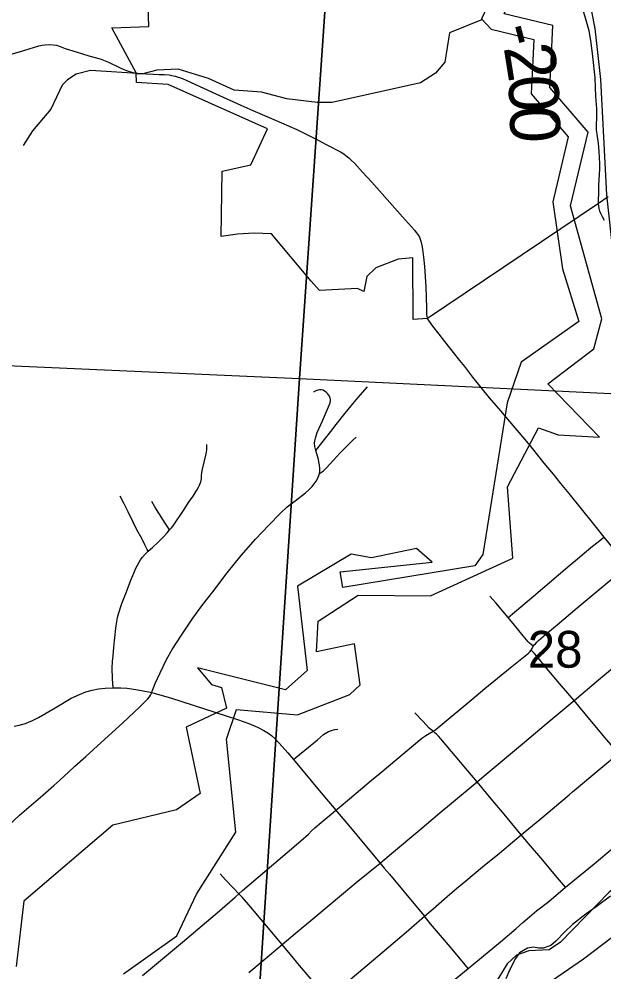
# Model space of a CAD drawing. Extents: x 0 to 34, y 0 to 22.
# Drawn here: x 6.959 to 7.626, y 19.29 to 20.375 of the extents above; entities that cross this region are included whole.
import ezdxf

# ---------------------------------------------------------------- set-up
doc = ezdxf.new("R2010")
doc.units = 0
for name, color, linetype in [('Default', 7, 'Continuous'), ('GM_X_City_Street', 7, 'Continuous'), ('GM_X_County_Road', 7, 'Continuous'), ('GM_X_Major_River', 7, 'Continuous'), ('GM_X_Minor_River', 7, 'Continuous'), ('GM_X_Rail_Line', 7, 'Continuous'), ('GM_X_Section', 7, 'Continuous'), ('GM_X_Section_Text', 7, 'Continuous'), ('GM_X_State_Route', 7, 'Continuous'), ('GM_X_Township_Road', 7, 'Continuous'), ('GM_X_Township_Road_Text', 7, 'Continuous'), ('SH_Text', 7, 'Continuous')]:
    doc.layers.add(name, color=color, linetype=linetype)

msp = doc.modelspace()

# ---------------------------------------------------------------- linework, layer by layer
at = {"layer": 'Default'}
for points in [[(7.3433, 20.9), (6.302, 20.9), (6.2522, 20.0112), (7.2788, 19.9659)], [(8.4029, 20.9), (7.3433, 20.9), (7.2788, 19.9659), (8.2644, 19.9182), (8.275, 19.9201), (8.2864, 19.9232), (8.3061, 19.9266), (8.3212, 19.9286), (8.3379, 19.9305), (8.3553, 19.9386)]]:
    msp.add_lwpolyline(points, close=True, dxfattribs=at)
for points in [[(6.9494, 18.7612), (7.0197, 18.8208), (7.0624, 18.8705), (7.2079, 18.9977), (7.3928, 19.1502), (7.4623, 19.2086), (7.6025, 19.305), (7.8528, 19.4948), (7.9095, 19.5426), (8.0081, 19.6871), (8.1321, 19.8131), (8.2273, 19.878), (8.3177, 19.9057), (8.4594, 19.9228), (8.5959, 19.9577), (8.7115, 19.9703), (8.8098, 20.0002), (8.9, 20.0446), (8.9, 20.9), (6.3032, 20.9)], [(7.6307, 20.1728), (7.6195, 20.1651), (7.4247, 20.034), (7.4085, 20.033), (7.4079, 20.1031), (7.3912, 20.1018), (7.366, 20.0917), (7.3557, 20.0818), (7.3521, 20.0648), (7.3451, 20.0682), (7.3017, 20.0659), (7.2923, 20.0766), (7.247, 20.1306), (7.2272, 20.1313), (7.2083, 20.1303), (7.1895, 20.1274), (7.1909, 20.2021), (7.2233, 20.209), (7.2425, 20.2502), (7.1291, 20.3008), (7.0932, 20.3031), (7.0929, 20.3138), (7.0649, 20.3652), (7.1073, 20.3667), (7.1065, 20.3898)], [(7.4623, 19.2086), (7.6025, 19.305), (7.8528, 19.4948), (7.9095, 19.5426), (8.0081, 19.6871), (8.1321, 19.8131), (8.2273, 19.878), (8.3177, 19.9057)]]:
    msp.add_lwpolyline(points, dxfattribs=at)
at = {"layer": 'GM_X_City_Street'}
for points in [[(7.1104, 19.6082), (7.111, 19.6097), (7.1124, 19.6135), (7.1145, 19.6185), (7.1199, 19.6306), (7.1273, 19.6458), (7.1336, 19.6571), (7.1443, 19.6736), (7.1574, 19.6929), (7.1687, 19.7086), (7.18, 19.7229), (7.1964, 19.7446), (7.2125, 19.7643), (7.2289, 19.783), (7.2438, 19.7988), (7.2569, 19.8121), (7.265, 19.8197), (7.2739, 19.8264), (7.2856, 19.8356), (7.2894, 19.839), (7.2932, 19.843), (7.2957, 19.846), (7.2978, 19.849), (7.2993, 19.8515), (7.3002, 19.8533), (7.3011, 19.8555), (7.3016, 19.8576), (7.3019, 19.8605), (7.302, 19.8632), (7.3017, 19.8673), (7.3011, 19.871), (7.3005, 19.8737), (7.2975, 19.8839), (7.2965, 19.8885), (7.2961, 19.8922), (7.2963, 19.8947), (7.297, 19.8979), (7.2992, 19.9044), (7.3051, 19.9176), (7.312, 19.9336), (7.3137, 19.9382), (7.3141, 19.9407), (7.3141, 19.942), (7.3138, 19.9436), (7.313, 19.9457), (7.312, 19.9474), (7.3108, 19.9489), (7.3094, 19.9501), (7.3074, 19.9515), (7.3057, 19.9524), (7.3036, 19.953), (7.3016, 19.953), (7.2997, 19.9526), (7.2975, 19.9516), (7.2949, 19.9501)], [(7.2975, 19.8839), (7.3145, 19.9054), (7.3205, 19.9133), (7.3308, 19.9265), (7.3376, 19.9348), (7.3455, 19.9439), (7.3564, 19.9565)], [(7.3016, 19.8576), (7.3038, 19.8591), (7.3061, 19.8608), (7.3082, 19.8625), (7.3097, 19.8641), (7.3133, 19.8682), (7.3179, 19.8733), (7.3247, 19.8808), (7.3402, 19.8961), (7.3433, 19.899)], [(7.0666, 19.6137), (7.0661, 19.6184), (7.0657, 19.6243), (7.0655, 19.6358), (7.0659, 19.6434), (7.0664, 19.65), (7.0673, 19.6595), (7.0682, 19.6672), (7.0689, 19.6738), (7.0697, 19.6813), (7.0706, 19.6892), (7.0715, 19.6935), (7.0726, 19.6978), (7.0765, 19.7095), (7.0816, 19.723), (7.0867, 19.7363), (7.09, 19.7442), (7.0925, 19.75), (7.0961, 19.7567), (7.0978, 19.7595), (7.0994, 19.7618), (7.1034, 19.7663), (7.1064, 19.769), (7.1113, 19.7734), (7.1177, 19.7796), (7.1238, 19.7854), (7.1282, 19.7902), (7.1308, 19.7933), (7.1328, 19.7957), (7.1347, 19.7981), (7.1372, 19.8016), (7.1403, 19.8061), (7.1427, 19.8097), (7.1473, 19.8168), (7.1524, 19.8245), (7.1575, 19.8318), (7.1599, 19.8355), (7.1619, 19.8388), (7.1637, 19.8419), (7.165, 19.8445), (7.1663, 19.848), (7.167, 19.8516), (7.1673, 19.855), (7.1676, 19.8586), (7.1682, 19.8624), (7.1723, 19.8786), (7.1729, 19.8818), (7.1732, 19.8849), (7.1733, 19.8907)], [(7.1064, 19.769), (7.1053, 19.7711), (7.1027, 19.7763), (7.099, 19.7835), (7.0934, 19.7936), (7.0888, 19.8028), (7.0835, 19.8139), (7.0786, 19.8238), (7.0745, 19.832)], [(7.1308, 19.7933), (7.1295, 19.7952), (7.1251, 19.8022), (7.1219, 19.8071), (7.1187, 19.8125), (7.1141, 19.8198), (7.1106, 19.8256)], [(7.5166, 19.6938), (7.5456, 19.7181), (7.5742, 19.7421), (7.5871, 19.7533), (7.5957, 19.7606), (7.6059, 19.7691), (7.6109, 19.7732), (7.6212, 19.7815), (7.6259, 19.7853)], [(7.0999, 19.286), (7.1273, 19.3088), (7.1454, 19.3239), (7.173, 19.3471), (7.1878, 19.3595), (7.2057, 19.3751), (7.2097, 19.3788), (7.2138, 19.3826), (7.2725, 19.4323), (7.2835, 19.4418), (7.2862, 19.4442), (7.2891, 19.447), (7.2926, 19.4505), (7.2965, 19.4542), (7.3034, 19.4602), (7.3149, 19.4697), (7.3204, 19.4742), (7.324, 19.4771), (7.3357, 19.487), (7.3611, 19.5085), (7.3707, 19.5164), (7.4185, 19.5561), (7.4227, 19.5591), (7.4268, 19.5617), (7.4311, 19.5641), (7.4342, 19.5661), (7.437, 19.5682), (7.4754, 19.6004), (7.4901, 19.6128), (7.519, 19.6365), (7.5398, 19.6531), (7.5414, 19.6546), (7.5429, 19.6564), (7.5442, 19.6585), (7.5454, 19.6608), (7.5465, 19.6624), (7.5477, 19.6638), (7.5493, 19.6656), (7.5514, 19.6676), (7.562, 19.6764), (7.5727, 19.6854), (7.5954, 19.7047), (7.6183, 19.7238), (7.6451, 19.7459)], [(7.5454, 19.6608), (7.5428, 19.6629), (7.5412, 19.6645), (7.5397, 19.666), (7.5338, 19.6729), (7.524, 19.6848), (7.5166, 19.6938), (7.5027, 19.7102), (7.496, 19.718)], [(7.709, 19.4587), (7.6991, 19.4705), (7.6925, 19.4784), (7.6791, 19.4945), (7.6664, 19.5098), (7.6557, 19.5226), (7.6424, 19.5388), (7.6393, 19.5426), (7.6292, 19.5544), (7.6099, 19.5775), (7.5918, 19.5992), (7.5754, 19.6186), (7.5609, 19.6357), (7.5491, 19.65), (7.5466, 19.6528), (7.5429, 19.6564)], [(6.9125, 19.4362), (6.9142, 19.4368), (6.9242, 19.4399), (6.9266, 19.4408), (6.9291, 19.442), (6.9315, 19.4434), (6.935, 19.4462), (6.941, 19.4511), (6.9598, 19.4685), (6.973, 19.4798), (6.9863, 19.4914), (6.9988, 19.5023), (7.0056, 19.5084), (7.0158, 19.5178), (7.0229, 19.5243), (7.0354, 19.5355), (7.0439, 19.5432), (7.0694, 19.5663), (7.0777, 19.5738), (7.0967, 19.5917), (7.1058, 19.6007), (7.1078, 19.6031), (7.1091, 19.6053), (7.1104, 19.6082)], [(7.4812, 19.5066), (7.4706, 19.5192), (7.452, 19.5412), (7.4401, 19.5556), (7.4375, 19.5584), (7.435, 19.5608), (7.4332, 19.5624), (7.4311, 19.5641), (7.4288, 19.5658), (7.4268, 19.5675), (7.4193, 19.5754), (7.4105, 19.5852)], [(7.2719, 19.5319), (7.2748, 19.5343), (7.2994, 19.5545), (7.3064, 19.5605), (7.3082, 19.5616), (7.3101, 19.5628), (7.3121, 19.5637), (7.3141, 19.5645), (7.3165, 19.5653), (7.3192, 19.566), (7.3225, 19.5665)], [(7.2593, 19.3214), (7.2411, 19.3425), (7.2211, 19.3664), (7.2135, 19.375), (7.2097, 19.3788), (7.2036, 19.3853), (7.1947, 19.395), (7.1886, 19.4017)]]:
    msp.add_lwpolyline(points, dxfattribs=at)
at = {"layer": 'GM_X_County_Road'}
for points in [[(7.4712, 19.294), (7.4863, 19.3065), (7.5078, 19.3244), (7.5259, 19.3395), (7.5336, 19.3464), (7.541, 19.3529), (7.5491, 19.3595), (7.5629, 19.3703), (7.5821, 19.3864), (7.6149, 19.4132), (7.6436, 19.4373), (7.6925, 19.4784), (7.7022, 19.4865), (7.7223, 19.5034), (7.7432, 19.521), (7.7704, 19.5437), (7.7927, 19.5626), (7.8028, 19.5712), (7.8078, 19.5755), (7.8446, 19.6061), (7.8689, 19.6264), (7.9009, 19.653), (7.914, 19.6641)], [(7.2211, 19.2895), (7.2374, 19.303), (7.2593, 19.3214), (7.274, 19.3338), (7.2941, 19.3504), (7.3289, 19.3796), (7.3436, 19.3919), (7.3707, 19.4139), (7.3713, 19.4144), (7.3836, 19.4248), (7.416, 19.4518), (7.4388, 19.4711), (7.4521, 19.4822), (7.4812, 19.5066), (7.4916, 19.5153), (7.5332, 19.5499), (7.5579, 19.5707), (7.5918, 19.5992), (7.6197, 19.6226), (7.6493, 19.6473)], [(7.5821, 19.3864), (7.5707, 19.3998), (7.5562, 19.4173), (7.5399, 19.4364), (7.5317, 19.446), (7.5263, 19.4527), (7.5121, 19.4698), (7.4975, 19.4872), (7.4812, 19.5066)], [(7.4712, 19.294), (7.4641, 19.3022), (7.4487, 19.3208), (7.4281, 19.3448), (7.4212, 19.3534)], [(7.3108, 19.2598), (7.3005, 19.2718), (7.2899, 19.2843), (7.279, 19.2973), (7.272, 19.3057), (7.2593, 19.3214)], [(7.3614, 19.2026), (7.3904, 19.2266), (7.4214, 19.2524), (7.4504, 19.2768), (7.4712, 19.294)]]:
    msp.add_lwpolyline(points, dxfattribs=at)
at = {"layer": 'GM_X_Major_River'}
msp.add_lwpolyline([(8.3728, 19.9358), (8.3456, 19.9259), (8.2425, 19.9091), (8.2002, 19.8972), (8.1417, 19.865), (8.0633, 19.804), (8.0019, 19.7441), (7.9196, 19.636), (7.8409, 19.5529), (7.8311, 19.546), (7.807, 19.5171), (7.7479, 19.4607), (7.6691, 19.4087), (7.6318, 19.3809), (7.5765, 19.3237), (7.5633, 19.3153), (7.5402, 19.3141), (7.5263, 19.3091), (7.5157, 19.2992), (7.5007, 19.2748)], dxfattribs=at)
at = {"layer": 'GM_X_Minor_River'}
for points in [[(7.093, 20.9), (7.1015, 20.8959), (7.1001, 20.8613), (7.0908, 20.8487), (7.1619, 20.8106), (7.2384, 20.7069), (7.2278, 20.6203), (7.3235, 20.554), (7.4067, 20.5259), (7.4198, 20.4497), (7.4421, 20.4321), (7.5005, 20.4053), (7.4865, 20.3756), (7.4973, 20.3635), (7.546, 20.3518), (7.5448, 20.3279), (7.543, 20.2899), (7.585, 20.241), (7.5676, 20.167)], [(7.5879, 20.1623), (7.6078, 20.2465), (7.5642, 20.2972), (7.5656, 20.3269), (7.5677, 20.368), (7.5122, 20.3813), (7.5283, 20.4154), (7.453, 20.45), (7.439, 20.4611), (7.4251, 20.5417), (7.333, 20.5728), (7.25, 20.6303), (7.2601, 20.7126), (7.1758, 20.8268), (7.1207, 20.8563), (7.1226, 20.9)], [(7.4874, 20.3745), (7.4497, 20.3596), (7.4444, 20.3261), (7.4338, 20.3135), (7.4167, 20.3025), (7.3163, 20.2803), (7.2992, 20.2803), (7.2643, 20.2845), (7.2355, 20.292), (7.2045, 20.2943), (7.1753, 20.3075), (7.1404, 20.3182), (7.1161, 20.317), (7.1002, 20.3128), (7.0407, 20.3165), (7.0244, 20.3123), (7.0146, 20.3058), (7.0085, 20.2998), (6.9956, 20.2724), (6.9744, 20.248), (6.9641, 20.2313)], [(7.5676, 20.167), (7.5787, 20.0906), (7.5973, 20.0308), (7.5315, 19.9843), (7.5154, 19.9382), (7.4877, 19.7653), (7.4787, 19.7523), (7.3283, 19.7278), (7.3251, 19.7456), (7.4301, 19.7568), (7.4124, 19.7722), (7.3609, 19.7615), (7.3377, 19.7658), (7.2767, 19.7292), (7.2878, 19.6333), (7.2631, 19.6111), (7.1625, 19.6364), (7.1787, 19.6172), (7.1898, 19.6139), (7.1958, 19.5904), (7.1497, 19.5687), (7.1655, 19.4933), (7.1385, 19.4745), (7.0662, 19.4572), (6.9648, 19.3705), (6.9559, 19.296)], [(7.0783, 19.288), (7.1392, 19.3311), (7.1614, 19.3787), (7.2064, 19.4493), (7.1955, 19.5551), (7.2072, 19.589), (7.2767, 19.5828), (7.3364, 19.6061), (7.348, 19.6168), (7.3417, 19.6638), (7.2982, 19.6547), (7.3, 19.6896), (7.3459, 19.7189), (7.4283, 19.7185), (7.5219, 19.7611), (7.5159, 19.8426), (7.5511, 19.9097), (7.5736, 19.9016), (7.621, 19.8989), (7.5618, 19.9599), (7.6144, 19.9998), (7.6235, 20.0337), (7.5879, 20.1623)]]:
    msp.add_lwpolyline(points, dxfattribs=at)
at = {"layer": 'GM_X_Rail_Line'}
msp.add_lwpolyline([(7.6079, 20.4037), (7.6154, 20.3643), (7.6219, 20.3065), (7.6288, 20.1751), (7.639, 20.0814), (7.6404, 20.069), (7.6476, 19.9967), (7.6582, 19.9566), (7.6756, 19.9331), (7.6894, 19.9155), (7.7108, 19.9039), (7.7417, 19.8954), (7.7465, 19.8956), (7.7777, 19.9004), (7.8811, 19.9164), (7.9343, 19.9288), (7.9734, 19.9429), (8.0106, 19.9643), (8.0481, 19.9954), (8.2404, 20.1565), (8.3206, 20.2117)], dxfattribs=at)
at = {"layer": 'GM_X_Section'}
msp.add_lwpolyline([(6.2522, 20.0112), (7.2788, 19.9659), (7.2183, 19.0454), (7.2111, 19.0396), (7.2009, 19.0309), (7.1911, 19.0218), (7.1794, 19.0123), (7.1605, 18.9948), (7.1379, 18.9735), (7.1205, 18.9571), (7.1137, 18.9506), (7.1073, 18.9438), (6.1895, 18.9865)], close=True, dxfattribs=at)
for points in [[(7.2183, 19.0454), (7.2788, 19.9659), (8.2644, 19.9182)], [(7.6332, 19.3761), (7.6169, 19.3642), (7.6056, 19.3563), (7.5901, 19.3441), (7.5814, 19.3357), (7.5712, 19.3251), (7.5652, 19.3201), (7.5565, 19.3171), (7.5516, 19.317), (7.5455, 19.3182), (7.5387, 19.317), (7.5296, 19.3117), (7.5251, 19.3052), (7.5183, 19.2919), (7.5142, 19.2821)]]:
    msp.add_lwpolyline(points, dxfattribs=at)
at = {"layer": 'GM_X_State_Route'}
for points in [[(7.5863, 19.4918), (7.5902, 19.495), (7.6223, 19.5219), (7.6424, 19.5388), (7.6512, 19.5462), (7.6962, 19.584), (7.7178, 19.6023), (7.748, 19.6275), (7.7528, 19.6315), (7.7622, 19.6394), (7.7932, 19.6655), (7.8182, 19.6865), (7.8434, 19.7077), (7.8636, 19.7244)], [(6.9536, 19.5699), (6.9595, 19.571), (6.9666, 19.573), (6.9706, 19.5747), (6.9738, 19.5761), (6.9814, 19.5799), (7.0004, 19.5908), (7.0188, 19.6016), (7.0281, 19.6059), (7.0355, 19.6088), (7.0425, 19.6108), (7.0499, 19.6124), (7.0573, 19.6133), (7.0666, 19.6137), (7.0751, 19.6136), (7.0823, 19.6132), (7.0945, 19.6114), (7.1066, 19.6091), (7.1104, 19.6082), (7.1172, 19.6065), (7.1317, 19.6021), (7.2083, 19.5773), (7.2212, 19.5728), (7.2311, 19.5687), (7.2384, 19.565), (7.2429, 19.5622), (7.2469, 19.5592), (7.2506, 19.5559), (7.2557, 19.5507), (7.2655, 19.5395), (7.2719, 19.5319), (7.3014, 19.4968), (7.3204, 19.4742), (7.3218, 19.4725), (7.3369, 19.4545)], [(7.4212, 19.3534), (7.4312, 19.362), (7.4472, 19.3758), (7.4579, 19.3849), (7.4684, 19.3937), (7.4874, 19.4097), (7.5069, 19.4251), (7.5317, 19.446), (7.5362, 19.4498), (7.5527, 19.4636), (7.5863, 19.4918)], [(7.3369, 19.4545), (7.3533, 19.4349), (7.3707, 19.4139), (7.3755, 19.4081), (7.3814, 19.4012)], [(7.3814, 19.4012), (7.413, 19.3632), (7.4212, 19.3534)], [(7.3108, 19.2598), (7.3129, 19.2615), (7.3201, 19.2675), (7.3286, 19.2747), (7.3344, 19.2795), (7.3534, 19.2954), (7.4004, 19.3351), (7.4212, 19.3534)]]:
    msp.add_lwpolyline(points, dxfattribs=at)
at = {"layer": 'GM_X_Township_Road'}
for points in [[(7.6197, 20.1646), (7.6198, 20.1704), (7.6199, 20.1754), (7.6202, 20.1859), (7.6211, 20.2046), (7.6212, 20.2106), (7.621, 20.2171), (7.6206, 20.2247), (7.6195, 20.2335), (7.618, 20.2442), (7.6175, 20.2487), (7.6175, 20.2538), (7.6176, 20.2637), (7.6177, 20.2732), (7.6168, 20.2868), (7.6159, 20.3084), (7.6132, 20.3326), (7.6114, 20.348), (7.6101, 20.3555), (7.6089, 20.3616), (7.6053, 20.3752), (7.5984, 20.3979)], [(6.9465, 20.3341), (6.9647, 20.3395), (6.9818, 20.3446), (6.9855, 20.3454), (6.9891, 20.346), (6.9934, 20.3463), (6.9983, 20.346), (7.002, 20.3453), (7.0061, 20.3439), (7.0119, 20.3418), (7.0243, 20.3379), (7.0387, 20.3334), (7.0516, 20.3297), (7.0612, 20.3262), (7.0746, 20.3198), (7.0787, 20.3179), (7.0827, 20.3164), (7.0878, 20.3146), (7.0931, 20.3132), (7.0941, 20.3132)], [(7.0941, 20.3132), (7.1046, 20.3127), (7.1125, 20.3125), (7.119, 20.3122), (7.1246, 20.312), (7.1303, 20.3115), (7.1335, 20.311), (7.1371, 20.3102), (7.1454, 20.3073), (7.1554, 20.3031), (7.1837, 20.2901), (7.212, 20.2773), (7.2258, 20.2712), (7.2497, 20.2607)], [(7.2497, 20.2607), (7.2758, 20.2493), (7.2987, 20.238), (7.3102, 20.232), (7.3162, 20.2289), (7.3203, 20.2267), (7.3257, 20.2238), (7.3293, 20.2216), (7.3322, 20.2195), (7.3353, 20.2171), (7.3379, 20.2145), (7.3418, 20.2107), (7.3508, 20.2009), (7.3613, 20.1895), (7.3907, 20.1565), (7.3963, 20.15), (7.4065, 20.1386), (7.41, 20.1347), (7.412, 20.1322), (7.4138, 20.1297), (7.4155, 20.1266), (7.4172, 20.1221), (7.4184, 20.1174), (7.4192, 20.1133), (7.4203, 20.1041), (7.4212, 20.0935), (7.4228, 20.0701), (7.4232, 20.0583), (7.4236, 20.046), (7.4238, 20.039), (7.4241, 20.0366), (7.4249, 20.0335)], [(7.6266, 20.1459), (7.6242, 20.15), (7.622, 20.1546), (7.6213, 20.1565), (7.6205, 20.1593), (7.62, 20.1622), (7.6197, 20.1646)], [(7.4249, 20.0335), (7.4258, 20.032), (7.4305, 20.0256), (7.4378, 20.0163), (7.4441, 20.0081), (7.4541, 19.9954), (7.4613, 19.9863), (7.4668, 19.9794), (7.4762, 19.9674), (7.4951, 19.9437), (7.5079, 19.9289), (7.5226, 19.912), (7.533, 19.8995), (7.5417, 19.889), (7.5486, 19.8804), (7.5573, 19.8695), (7.568, 19.8567), (7.5765, 19.8464), (7.586, 19.8347), (7.6138, 19.7999), (7.6259, 19.7853), (7.6399, 19.7681), (7.6487, 19.7571), (7.6527, 19.7521)]]:
    msp.add_lwpolyline(points, dxfattribs=at)
at = {"layer": 'SH_Text'}
msp.add_lwpolyline([(6.9494, 18.7612), (7.0197, 18.8208), (7.0624, 18.8705), (7.2079, 18.9977), (7.3928, 19.1502), (7.4623, 19.2086), (7.6025, 19.305), (7.8528, 19.4948), (7.9095, 19.5426), (8.0081, 19.6871), (8.1321, 19.8131), (8.2273, 19.878), (8.3177, 19.9057), (8.4594, 19.9228), (8.5959, 19.9577), (8.7115, 19.9703), (8.8098, 20.0002), (8.9, 20.0446), (8.9, 20.9), (2.1, 20.9)], dxfattribs=at)

# ---------------------------------------------------------------- texts
at = {"layer": 'GM_X_Section_Text'}
msp.add_text('28', height=0.04186, rotation=0, dxfattribs=at).set_placement((7.5391, 19.6365))
at = {"layer": 'GM_X_Township_Road_Text'}
for s, rotation, p in [('-', 284.4281, (7.5059, 20.3645)), ('2', 279.0405, (7.5115, 20.3432)), ('0', 272.629, (7.5168, 20.3103)), ('0', 271.6238, (7.5184, 20.2756))]:
    msp.add_text(s, height=0.0568, rotation=rotation, dxfattribs=at).set_placement(p)

doc.saveas('drawing.dxf')
